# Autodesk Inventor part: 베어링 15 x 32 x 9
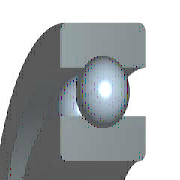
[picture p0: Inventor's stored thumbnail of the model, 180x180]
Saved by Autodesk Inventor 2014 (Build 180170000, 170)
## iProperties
IsCustomPart: 0
Created: 2012-02
Part Number: 베어링 15 x 32 x 9
Material: 강철, 연강
Description: 깊은 그루브 볼 베어링
Document SubType Name: Modeling
Standard: KS B 2023
Designer: mduedu
Standards Organization: KS
Language: ko-KR
Size Designation: 6002 - 15 x 32 x 9
Categories: <MemberInstance><Categories><Category DisplayName="샤프트 부품" InternalName="7f7aeb1f-a693-4053-b835-cee3144e0d98" Mnemonic="SHFT"><Category DisplayName="베어링" Inter
Density: 1 g/cm^3
Appearance: 노란색
Author: mduedu
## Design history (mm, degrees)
sketch "스케치" dims "d0" = 4.42 (= -0.26 x WD + 0.26 x BD)
  geometry: L1 (2.29, 11.75)-(6.71, 11.75); L2 (4.5, 11.75)-(4.5, 9.54); L3 (4.5, 11.75)-(4.5, 13.96); L4 (2.858, 10.271)-(0, 10.271); L5 (0, 7.5)-(9, 7.5); L6 (2.858, 13.229)-(0, 13.229); L7 (0, 16)-(9, 16); L8 (9, 7.5)-(9, 10.271); L9 (6.142, 10.271)-(9, 10.271); L10 (6.142, 13.229)-(9, 13.229); L11 (9, 16)-(9, 13.229); L12 (-1.4, 0)-(8.4, 0) reference; L13 (0, -0.3)-(0, 5.3) reference
  constraints: 22 end point, 4 point on line, 2 collinear, 2 perpendicular, 2 symmetric about line, 1 midpoint, 1 parallel, 14 other
  dimensions: "d9" = 15 diameter of L5 L12 (= WD); "d11" = 32 diameter of L7 L12 (= BD); "d12" = 9 distance between parallel lines of L8 L13 (= KB); "d13" = 20.542 diameter of L9 L12 (= 0.326 x BD + 0.674 x WD)
revolve "본체" stored, may be unused: angle "d6" = 90 deg
revolve "볼" stored, may be unused: angle "d7" = 90 deg
pattern_circular "IDS_ARRAYBALL[SIMPL:T]" dims angle "d3" = 360 deg
body "Solid1"
fillet "모깎기1" dims "d1" = 0.3 (= KRS)
other parameters: "WD" = 15 [user parameter; used in 5 equation terms], "BD" = 32 [user parameter; used in 5 equation terms], "KB" = 9 [user parameter; used in 1 equation term], "KRS" = 0.3 [user parameter; used in 1 equation term], "d4" = 0, "d5" = 0, "d8" = 0, "d14" = 0, "d15" = 0, "BBA" = 0 [user parameter], "BC0" = 2850000 [user parameter], "BC" = 5590000 [user parameter], "BR" = 16 (= 0.5 x BD) [user parameter], "WR" = 7.5 (= 0.5 x WD) [user parameter]
